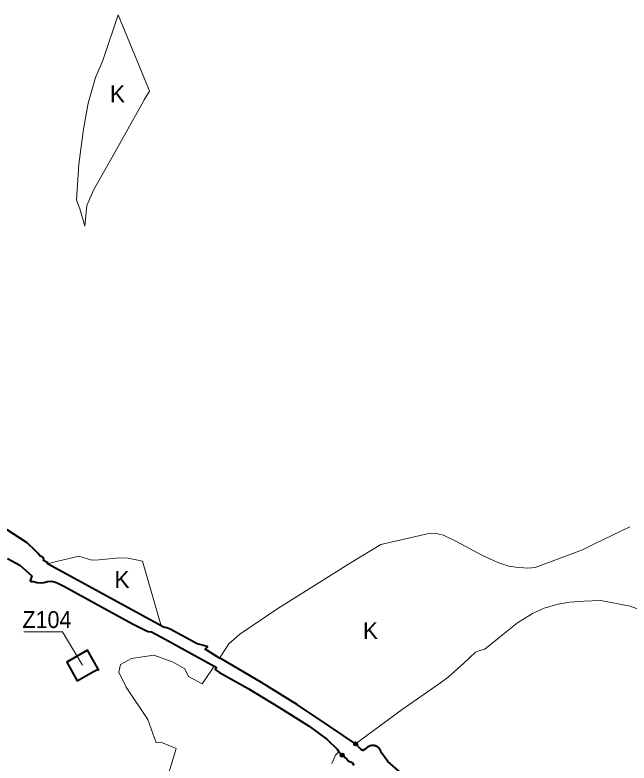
# Model space of a CAD drawing. Extents: x -650276 to -642489, y -1074311 to -1066658.
# Drawn here: x -646064 to -645192, y -1069193 to -1068130 of the extents above; entities that cross this region are included whole.
import ezdxf

# ---------------------------------------------------------------- set-up
doc = ezdxf.new("R2010")
doc.units = 0
doc.header["$LTSCALE"] = 9.6
doc.header["$PDMODE"] = 32
doc.header["$PDSIZE"] = 4.8
for name, color, linetype, lineweight in [('44', 7, 'Continuous', 40), ('45', 7, 'Continuous', 40), ('46', 7, 'Continuous', 13), ('47', 7, 'Continuous', 13), ('48', 7, 'Continuous', 13), ('63', 7, 'Continuous', 13)]:
    doc.layers.add(name, color=color, linetype=linetype, lineweight=lineweight)

msp = doc.modelspace()

# ---------------------------------------------------------------- linework, layer by layer
at = {"layer": '44'}
for points in [[(-645579.94, -1069165.52), (-645616.63, -1069140.8), (-645662.44, -1069109.89), (-645713.61, -1069078.06), (-645770.04, -1069045.34), (-645773.38, -1069043.46), (-645793.638, -1069031.021), (-645790.53, -1069027.19), (-645805.16, -1069023.52), (-645843.56, -1069002.41), (-645848.18, -1069000.48), (-645852.91, -1068999.62), (-645856.26, -1068997.79), (-645892.77, -1068977.86), (-645933.28, -1068955.74), (-645975.31, -1068932.8), (-646017.55, -1068909.75), (-646017.39, -1068908.42), (-646023.56, -1068905.05), (-646023.13, -1068903.12), (-646023.92, -1068900.73), (-646025.57, -1068899.39), (-646028.18, -1068898.89), (-646031.31, -1068894.32), (-646034.65, -1068891.12), (-646046.48, -1068879.92), (-646074.78, -1068861.51)], [(-646074.51, -1068901.9), (-646057.13, -1068911.62), (-646039.84, -1068926.67), (-646042.5, -1068933.91), (-646040.65, -1068934.59), (-646037.5, -1068934.7), (-646032.61, -1068936.1)], [(-646032.61, -1068936.1), (-646027.69, -1068936.6), (-646022.77, -1068936.12), (-646017.6, -1068934.89), (-646012.64, -1068934.34), (-646007.7, -1068935.18), (-646002.95, -1068936.95), (-645993.5, -1068942.1), (-645940.77, -1068970.74), (-645896.91, -1068994.75), (-645879.17, -1069004.02), (-645874.49, -1069005.73), (-645869.83, -1069006.45), (-645850.79, -1069016.84), (-645803.29, -1069042.92), (-645781.12, -1069055.29), (-645777.73, -1069057.2), (-645779.49, -1069059.92), (-645773.29, -1069063.99), (-645732.65, -1069086.82), (-645688.87, -1069113.44), (-645646.08, -1069140.37), (-645620.2, -1069159.26), (-645606.11, -1069172.98), (-645603.91, -1069176.86), (-645599, -1069181.48)], [(-645571.9, -1069173.43), (-645579.94, -1069165.52), (-645579.94, -1069165.52)], [(-645543.43, -1069178.39), (-645543.547, -1069177.727), (-645543.706, -1069177.053), (-645543.907, -1069176.37), (-645544.154, -1069175.682), (-645544.448, -1069174.993), (-645544.792, -1069174.308), (-645545.186, -1069173.63), (-645545.631, -1069172.966), (-645546.127, -1069172.32), (-645546.674, -1069171.699), (-645547.269, -1069171.107), (-645547.91, -1069170.551), (-645548.594, -1069170.034), (-645549.317, -1069169.563), (-645550.076, -1069169.141), (-645550.863, -1069168.772), (-645551.674, -1069168.459), (-645552.504, -1069168.203), (-645553.344, -1069168.007), (-645554.191, -1069167.87), (-645555.036, -1069167.793), (-645555.875, -1069167.772), (-645556.702, -1069167.808), (-645557.511, -1069167.896), (-645558.298, -1069168.035), (-645559.06, -1069168.219), (-645559.793, -1069168.445), (-645560.494, -1069168.709), (-645561.162, -1069169.007), (-645561.794, -1069169.334), (-645562.39, -1069169.686), (-645562.95, -1069170.06), (-645567.5, -1069173.46), (-645569.81, -1069175.03), (-645571.9, -1069173.43)], [(-645599, -1069181.48), (-645599, -1069181.48), (-645592.24, -1069187.73), (-645590.41, -1069189.45), (-645584.73, -1069191.88), (-645582.63, -1069195.88)], [(-645184.88, -1069596.58), (-645202.56, -1069568.23), (-645230.1, -1069525.98), (-645253.4, -1069493.06), (-645278.31, -1069461.33), (-645281.4, -1069458.4), (-645290.5, -1069449.03), (-645299.61, -1069437.97), (-645306.16, -1069425.55), (-645314.14, -1069412.54), (-645321.1, -1069405.21), (-645326.59, -1069396.64), (-645350.63, -1069363.98), (-645371.12, -1069339.47), (-645376.38, -1069332.65), (-645400.07, -1069313.32), (-645424.8, -1069295.24), (-645458.45, -1069265.56), (-645494.13, -1069227.63), (-645515.89, -1069206.66), (-645534.25, -1069190.56), (-645543.43, -1069178.39)]]:
    msp.add_lwpolyline(points, dxfattribs=at)
for p in [(-645579.94, -1069165.52), (-645599, -1069181.48)]:
    msp.add_point(p, dxfattribs=at)
at = {"layer": '45'}
for points in [[(-645944.69, -1069060.7), (-645960.67, -1069032.26), (-645990.13, -1069049.3), (-645975.48, -1069075.71), (-645952.21, -1069062.4)], [(-645944.69, -1069060.7), (-645960.67, -1069032.26), (-645990.13, -1069049.3), (-645975.48, -1069075.71), (-645952.21, -1069062.4)], [(-645952.21, -1069062.4), (-645946.84, -1069059.58), (-645944.69, -1069060.7)], [(-645952.21, -1069062.4), (-645946.84, -1069059.58), (-645944.69, -1069060.7)]]:
    msp.add_lwpolyline(points, dxfattribs=at)
at = {"layer": '46'}
msp.add_lwpolyline([(-646051.21, -1069006.26), (-645996.286, -1069006.26), (-645968.211, -1069053.466)], dxfattribs=at)
msp.add_lwpolyline([(-646051.21, -1069006.26), (-645996.286, -1069006.26), (-645968.211, -1069053.466)], dxfattribs=at)
at = {"layer": '47'}
msp.add_lwpolyline([(-645874.15, -1068234.44), (-645917.44, -1068129.99), (-645938.87, -1068193.06), (-645941.41, -1068200.54), (-645949.52, -1068218.72), (-645959.76, -1068255.23), (-645966.56, -1068292.38), (-645973.25, -1068342.08), (-645976.63, -1068393.14), (-645971.94, -1068405.38), (-645964.53, -1068429.83), (-645963.12, -1068415.21), (-645961.7, -1068400.54), (-645952.21, -1068378.95), (-645926.06, -1068332.18), (-645883.87, -1068256.88), (-645880.28, -1068250.47), (-645872.64, -1068238.08)], close=True, dxfattribs=at)
for points in [[(-645544.33, -1068882.17), (-645500.83, -1068872.25), (-645473.89, -1068866.13), (-645462.97, -1068866.88), (-645455.34, -1068868.9), (-645436.72, -1068877.85), (-645400.92, -1068897.18), (-645379.06, -1068907.27), (-645362.84, -1068912.83), (-645352.46, -1068914.25), (-645335.45, -1068915.77)], [(-645239.85, -1068880.94), (-645190.22, -1068857.23)], [(-645426.3, -1069051.02), (-645448.49, -1069070.45), (-645459.5, -1069078.59), (-645514.08, -1069116.5), (-645579.94, -1069165.52), (-645616.63, -1069140.8), (-645662.44, -1069109.89), (-645694.447, -1069089.98), (-645713.61, -1069078.06), (-645770.04, -1069045.34), (-645773.38, -1069043.46), (-645760.07, -1069023.11), (-645744.65, -1069009.71), (-645690.34, -1068973.16), (-645586.28, -1068907.71), (-645544.33, -1068882.17)], [(-645335.45, -1068915.77), (-645324.79, -1068914.82), (-645257.5, -1068889.68), (-645239.85, -1068880.94)], [(-645973.36, -1068898.93), (-645980.93, -1068900.85), (-645994.9, -1068904.1), (-646004.88, -1068906.5), (-646010.48, -1068907.86), (-646017.55, -1068909.75), (-645975.31, -1068932.8), (-645933.28, -1068955.74)], [(-645882.63, -1068905.88), (-645902.91, -1068901.43), (-645915.61, -1068901.02), (-645930.1, -1068902.47), (-645944.23, -1068904.13), (-645954.59, -1068904.41), (-645973.36, -1068898.93)], [(-645933.28, -1068955.74), (-645892.77, -1068977.86), (-645856.26, -1068997.79), (-645882.63, -1068905.88)], [(-645131.73, -1068995.69), (-645159.37, -1068981.11), (-645189.84, -1068969.91), (-645229.27, -1068962.28), (-645232.4, -1068961.67), (-645255.21, -1068962.49), (-645275.45, -1068964.38), (-645292.77, -1068966.91), (-645311.99, -1068972.74), (-645328.55, -1068980.37), (-645350.17, -1068993.33), (-645371.35, -1069010.64), (-645396.53, -1069030.88)], [(-645396.53, -1069030.88), (-645405.02, -1069033.34), (-645409.61, -1069035.17), (-645426.3, -1069051.02)], [(-645797.957, -1069080.052), (-645817.59, -1069069.6), (-645822.85, -1069058.8), (-645838.99, -1069049.31), (-645866.69, -1069039.37), (-645898.57, -1069044.24), (-645913.8, -1069052.51), (-645916.2, -1069063.8), (-645905.94, -1069085.11), (-645874.98, -1069131.01), (-645863.38, -1069163.79), (-645856.76, -1069163.17), (-645835.157, -1069172.184)], [(-645613.9, -1069193.45), (-645608.71, -1069181.51), (-645603.91, -1069176.86), (-645606.11, -1069172.98), (-645620.2, -1069159.26), (-645646.08, -1069140.37), (-645688.87, -1069113.44), (-645732.65, -1069086.82), (-645773.29, -1069063.99), (-645779.49, -1069059.92), (-645777.73, -1069057.2), (-645781.12, -1069055.29), (-645784.69, -1069060.74), (-645797.957, -1069080.052)], [(-645835.157, -1069172.184), (-645859.43, -1069254.08), (-645864.96, -1069269.78), (-645867.42, -1069274.21), (-645866.45, -1069276.32), (-645877.15, -1069319.06), (-645877.15, -1069319.06), (-645889.29, -1069330.52), (-645921.56, -1069346.6), (-645935.33, -1069340.64), (-645938.89, -1069341.56), (-645938.399, -1069347.452)]]:
    msp.add_lwpolyline(points, dxfattribs=at)
at = {"layer": '63'}
for points in [[(-645944.69, -1069060.7), (-645960.67, -1069032.26), (-645990.13, -1069049.3)], [(-645990.13, -1069049.3), (-645975.48, -1069075.71), (-645975.48, -1069075.71)], [(-645975.48, -1069075.71), (-645952.21, -1069062.4), (-645946.84, -1069059.58), (-645944.69, -1069060.7)]]:
    msp.add_lwpolyline(points, dxfattribs=at)

# ---------------------------------------------------------------- texts
at = {"layer": '46', "width": 0.95}
msp.add_text('Z104', height=24, dxfattribs=at).set_placement((-646053.286, -1069000.877))
msp.add_text('Z104', height=24, dxfattribs=at).set_placement((-646053.286, -1069000.877))
at = {"layer": '48'}
for p in [(-645928.983, -1068254.123), (-645928.983, -1068254.123), (-645922.543, -1068943.866), (-645922.543, -1068943.866), (-645569.606, -1069016.557), (-645569.606, -1069016.557)]:
    msp.add_text('K', height=24, dxfattribs=at).set_placement(p)

doc.saveas('drawing.dxf')
